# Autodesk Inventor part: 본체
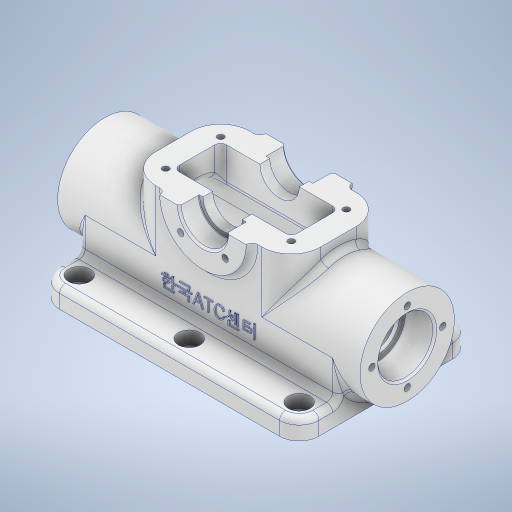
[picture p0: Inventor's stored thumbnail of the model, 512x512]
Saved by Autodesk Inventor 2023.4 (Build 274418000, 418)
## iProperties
Created: 2024-06
Part Number: 본체
Material: 알루미늄 6061
Document SubType Name: Modeling
Designer: user
Density: 2.7 g/cm^3
Appearance: 알루미늄 - 평지
Mass: 551.897 g
Surface Area: 613.714 cm^2
Volume: 204.406 cm^3
Author: user
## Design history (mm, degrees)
sketch "스케치1"
  geometry: L1 (66, 44)-(-66, 44); L2 (-66, 44)-(-66, -44); L3 (-66, -44)-(66, -44); L4 (66, -44)-(66, 44); L5 (66, 44)-(-66, -44); L6 (-66, 44)-(66, -44); 1 further point
  constraints: 12 end point, 2 midpoint, 2 parallel, 1 horizontal, 1 perpendicular
  dimensions: "d0" = 132 distance of L2.end L3.end; "d1" = 88 distance of L1.end L2.end
extrude "돌출1" new body sketch "스케치1" distance "d2" = 10; taper "d3" = 0 deg
sketch "스케치2"
  geometry: L1 (0, -44)-(0, 44) reference; C1 r 24 at (28, 0); 2 further points
  constraints: 1 centre point, 1 horizontal alignment, 1 midpoint
  dimensions: "d4" = 48 diameter of C1; "d5" = 28 distance from line of L1 C1.centre
extrude "돌출2" join sketch "스케치2" stored distance "d6" = 154; taper "d7" = 0 deg
sketch "스케치3"
  geometry: L1 (10, 44)-(10, 15.875) reference; L2 (28, -24)-(10, -24); L3 (10, -24)-(10, 24); L4 (10, 24)-(28, 24); L5 (28, 24)-(28, -24); A1 r 24 centre (28, 0) between (28, -24) and (10, 15.875) reference; A2 r 24 centre (28, 0) between (28, -24) and (10, 15.875) reference; 3 further points
  constraints: 8 end point, 2 parallel, 2 tangent, 1 horizontal, 1 perpendicular, 1 point on circle, 1 point on line
extrude "돌출3" join sketch "스케치3" stored distance "d8" = 132; taper "d9" = 0 deg
node "작업 평면1"
sketch "스케치4"
  geometry: L1 (108, 0)-(24, 0); L2 (24, 0)-(24, -48); L3 (24, -48)-(108, -48); L4 (108, -48)-(108, 0); L5 (132, -48)-(0, -48) reference; L6 (0, -48)-(-11, -48) reference; L7 (-11, -48)-(-11, 0) reference; L8 (-11, 0)-(0, 0) reference; L9 (0, 0)-(132, 0) reference; L10 (132, 0)-(143, 0) reference; L11 (143, 0)-(143, -48) reference; L12 (143, -48)-(132, -48) reference; 1 further point
  constraints: 8 end point, 2 parallel, 2 point on line, 1 horizontal, 1 perpendicular
  dimensions: "d10" = 84 distance between parallel lines of L2 L4; "d11" = 42 distance from line of point (66, -24) L2
extrude "돌출4" join sketch "스케치4" distance "d12" = 31; taper "d13" = 0 deg
sketch "스케치5"
  geometry: L1 (66, 0)-(-66, 0) reference; L2 (-66, 4)-(-77, 4) reference; L3 (-77, 4)-(-77, 52) reference; L4 (-77, 52)-(-42, 52) reference; L5 (-42, 52)-(-42, 59) reference; L6 (-42, 59)-(42, 59) reference; L7 (42, 59)-(42, 52) reference; L8 (42, 52)-(77, 52) reference; L9 (77, 52)-(77, 4) reference; L10 (77, 4)-(66, 4) reference; L11 (66, 4)-(66, 0) reference; L12 (66, 0)-(-66, 0) reference; L13 (-66, 0)-(-66, 4) reference; C1 r 22 at (0, 59); 4 further points
  constraints: 1 centre point, 1 midpoint, 1 vertical alignment
  dimensions: "d14" = 44 diameter of C1; "d15" = 59 distance from line of L1 C1.centre
extrude "돌출5" join sketch "스케치5" stored distance "d16" = 54; taper "d17" = 0 deg
sketch "스케치6"
  geometry: L1 (37, -27)-(59, -27) reference; L2 (47, -27)-(47, -17); L3 (47, -17)-(49, -17); L4 (49, -17)-(49, 17); L5 (49, 17)-(47, 17); L6 (47, 17)-(47, 27); L7 (59, 27)-(37, 27) reference; L8 (59, -27)-(59, 27); 1 further point
  constraints: 12 end point, 4 point on line, 3 perpendicular, 2 vertical
  dimensions: "d18" = 24 diameter of L2 L8; "d19" = 20 diameter of L4 L8; "d20" = 10 distance of L5.end L6.end; "d21" = 10 distance of L2.start L2.end
revolve "회전1" sketch "스케치6" stored, may be unused: angle "d22" = 90 deg
sketch "스케치7"
  geometry: L1 (36, -12)-(96, -12); L2 (96, -12)-(96, -36); L3 (96, -36)-(36, -36); L4 (36, -36)-(36, -12); L5 (36, -12)-(96, -36); L6 (96, -12)-(36, -36); 1 further point
  constraints: 12 end point, 2 midpoint, 2 parallel, 1 horizontal, 1 perpendicular
  dimensions: "d23" = 60 distance between parallel lines of L4 L2; "d24" = 24 distance of L3.end L1.start
extrude "돌출6" cut sketch "스케치7" extent not by distance; stored distance "d25" = 0; taper "d26" = 0 deg
sketch "스케치8"
  geometry: L1 (0, 44)-(0, -44) reference; L2 (28, -18)-(0, -18); L3 (28, 18)-(0, 18); A1 r 18 centre (28, 0) between (28, -18) and (28, 18); 2 further points
  constraints: 4 end point, 2 point on circle, 2 point on line, 2 tangent, 1 centre point, 1 horizontal, 1 horizontal alignment, 1 midpoint, 1 perpendicular
  dimensions: "d27" = 36 diameter of A1; "d28" = 28 distance from line of L1 A1.centre
extrude "돌출7" cut sketch "스케치8" stored distance "d29" = 120; taper "d30" = 0 deg
sketch "스케치9"
  geometry: L1 (-77, 52)-(-77, 4) reference; L2 (-77, 42)-(-62, 42); L3 (-62, 42)-(-62, 39); L4 (-62, 39)-(-60, 39); L5 (-60, 46)-(-60, 28) reference; L6 (77, 4)-(77, 52) reference; L7 (77, 42)-(62, 42); L8 (62, 42)-(62, 39); L9 (62, 39)-(60, 39); L10 (77, 4)-(66, 4) reference; L11 (66, 4)-(66, 0) reference; L12 (66, 0)-(60, 0) reference; L13 (60, 0)-(60, 46) reference; L14 (60, 46)-(30, 46) reference; L15 (30, 46)-(30, 59) reference; L16 (30, 59)-(42, 59) reference; L17 (42, 59)-(42, 52) reference; L18 (42, 52)-(77, 52) reference; L19 (77, 52)-(77, 4) reference; L20 (-66, 4)-(-77, 4) reference; L21 (-77, 4)-(-77, 52) reference; L22 (-77, 52)-(-42, 52) reference; L23 (-42, 52)-(-42, 59) reference; L24 (-42, 59)-(-30, 59) reference; L25 (-30, 59)-(-30, 46) reference; L26 (-30, 46)-(-60, 46) reference; L27 (-60, 46)-(-60, 0) reference; L28 (-60, 0)-(-66, 0) reference; L29 (-66, 0)-(-66, 4) reference; L30 (-77, 28)-(77, 28); 5 further points
  constraints: 14 end point, 6 point on line, 2 horizontal, 2 midpoint, 2 perpendicular, 1 vertical
  dimensions: "d31" = 28 diameter of L7 L30; "d32" = 22 diameter of L9 L30; "d33" = 28 diameter of L2 L30; "d34" = 15 distance of L2.start L2.end; "d35" = 15 distance of L7.start L7.end
revolve "회전2" sketch "스케치9" stored, may be unused: angle "d36" = 90 deg
fillet "모깎기1" dims "d37" = 0.3
fillet "모깎기2" dims "d38" = 15
fillet "모깎기3" dims "d39" = 3
sketch "스케치10"
  geometry: L1 (0, -10)-(132, -10) reference; L2 (41.419, 13.539)-(91.194, 13.539); L3 (91.194, 13.539)-(91.194, 6.334); L4 (91.194, 6.334)-(41.419, 6.334); L5 (41.419, 6.334)-(41.419, 13.539); 3 further points
  constraints: 1 midpoint, 1 vertical alignment, 2 other
  dimensions: "d40" = 20 distance from line of L1 point (66, 10)
feature "엠보싱1" sketch "스케치10" dims "d41" = 0.5, "d42" = 0
sketch "스케치11" dims "d10" = 84, "d11" = 42
  geometry: C1 r 14 at (0, 0) reference; A1 r 18 centre (0, 0) between (-12, 13.416) and (12, 13.416); A2 r 18 centre (0, 0) between (12, 13.416) and (-12, 13.416) reference; 2 further points
  constraints: 1 centre point, 1 coincident, 1 point on circle
  dimensions: "d43" = 36 diameter of A1
hole "구멍1" sketch "스케치11" at (0, 18) diameter "d44" = 3.242; stored, may be unused: countersink angle "d48" = 90 deg, drill point angle "d50" = 118 deg; dims "d45" = 8, "d46" = 4, "d47" = 2, "d49" = 10
fillet "모깎기4" dims "d54" = 10
fillet "모깎기5" dims "d55" = 3
fillet "모깎기6" dims "d56" = 3
fillet "모깎기7" dims "d57" = 3
fillet "모깎기8" dims "d58" = 3
fillet "모깎기9" dims "d59" = 3
sketch "스케치12"
  geometry: L1 (77.7, -41)-(76, -41) reference; L2 (76, -41)-(76, -36) reference; L3 (76, -36)-(93, -36) reference; L4 (96, -33)-(96, -15) reference; L5 (93, -12)-(76, -12) reference; L6 (76, -12)-(76, -7) reference; L7 (76, -7)-(77.7, -7) reference; L8 (78, -6.7)-(78, 3) reference; L9 (78, 3)-(88, 3) reference; L10 (88, 3)-(88, 0) reference; L11 (88, 0)-(93, 0) reference; L12 (108, -15)-(108, -33) reference; L13 (93, -48)-(88, -48) reference; L14 (88, -48)-(88, -51) reference; L15 (88, -51)-(78, -51) reference; L16 (78, -51)-(78, -41.3) reference; L17 (54, -41.3)-(54, -51) reference; L18 (54, -51)-(44, -51) reference; L19 (44, -51)-(44, -48) reference; L20 (44, -48)-(39, -48) reference; L21 (24, -33)-(24, -15) reference; L22 (39, 0)-(44, 0) reference; L23 (44, 0)-(44, 3) reference; L24 (44, 3)-(54, 3) reference; L25 (54, 3)-(54, -6.7) reference; L26 (54.3, -7)-(56, -7) reference; L27 (56, -7)-(56, -12) reference; L28 (56, -12)-(39, -12) reference; L29 (36, -15)-(36, -33) reference; L30 (39, -36)-(56, -36) reference; L31 (56, -36)-(56, -41) reference; L32 (56, -41)-(54.3, -41) reference; L33 (98, -38)-(34, -38); L34 (34, -38)-(34, -10); L35 (34, -10)-(98, -10); L36 (98, -10)-(98, -38); A1 r 0.3 centre (77.7, -41.3) between (78, -41.3) and (77.7, -41) reference; A2 r 3 centre (93, -33) between (93, -36) and (96, -33) reference; A3 r 3 centre (93, -15) between (96, -15) and (93, -12) reference; A4 r 0.3 centre (77.7, -6.7) between (77.7, -7) and (78, -6.7) reference; A5 r 15 centre (93, -15) between (108, -15) and (93, 0) reference; A6 r 15 centre (93, -33) between (93, -48) and (108, -33) reference; A7 r 0.3 centre (54.3, -41.3) between (54.3, -41) and (54, -41.3) reference; A8 r 15 centre (39, -33) between (24, -33) and (39, -48) reference; A9 r 15 centre (39, -15) between (39, 0) and (24, -15) reference; A10 r 0.3 centre (54.3, -6.7) between (54, -6.7) and (54.3, -7) reference; A11 r 3 centre (39, -15) between (39, -12) and (36, -15) reference; A12 r 3 centre (39, -33) between (36, -33) and (39, -36) reference; 1 further point
  constraints: 8 end point, 2 parallel, 1 horizontal, 1 perpendicular
  dimensions: "d60" = 64 distance of L33.start L33.end; "d61" = 28 distance of L33.end L34.end; "d62" = 32 distance from line of point (66, -24) L34; "d63" = 14 distance from line of L35 point (66, -24)
hole "구멍2" sketch "스케치12" at (98, -38), (34, -38), (34, -10), (98, -10) diameter "d64" = 3.242; stored, may be unused: countersink angle "d68" = 90 deg, drill point angle "d70" = 118 deg; dims "d65" = 8, "d66" = 4, "d67" = 2, "d69" = 10
sketch "스케치13" dims "d71" = 32
  geometry: L1 (0, 59)-(0, 37); L2 (0, 59)-(-11.314, 47.686); A1 r 10 centre (0, 59) between (-10, 59) and (10, 59) reference; A2 r 22 centre (0, 59) between (-22, 59) and (22, 59) reference; 2 further points
  constraints: 4 end point, 1 coincident, 1 point on circle, 1 vertical, 3 other
  dimensions: "d72" = 45 deg angle of L1 L2
hole "구멍3" sketch "스케치13" at (-11.314, 47.686) diameter "d73" = 3.242; stored, may be unused: countersink angle "d77" = 90 deg, drill point angle "d79" = 118 deg; dims "d74" = 8, "d75" = 4, "d76" = 2, "d78" = 10
fillet "모깎기10" dims "d83" = 3
fillet "모깎기11" dims "d84" = 3
sketch "스케치14"
  geometry: L1 (56, -34)-(-56, -34); L2 (-56, -34)-(-56, 34); L3 (-56, 34)-(56, 34); L4 (56, 34)-(56, -34); L5 (-60, 15)-(-60, -15) reference; L6 (-57, -18)-(57, -18) reference; L7 (60, -15)-(60, 15) reference; L8 (57, 18)-(-57, 18) reference; L9 (-66.026, 0)-(-67, 1.621) reference; L10 (-67, 1.621)-(-77, 1.621) reference; L11 (-77, 1.621)-(-77, 15.875) reference; L12 (-77, 15.875)-(-69, 15.875) reference; L13 (-66, 20.125)-(-66, 21.804) reference; L14 (-63, 34)-(-63, 27) reference; L15 (56, 41)-(-56, 41) reference; L16 (63, 27)-(63, 34) reference; L17 (66, 21.804)-(66, 20.125) reference; L18 (69, 15.875)-(77, 15.875) reference; L19 (77, 15.875)-(77, 1.621) reference; L20 (77, 1.621)-(67, 1.621) reference; L21 (67, 1.621)-(66.026, 0) reference; L22 (66.026, 0)-(67, -1.621) reference; L23 (67, -1.621)-(77, -1.621) reference; L24 (77, -1.621)-(77, -15.875) reference; L25 (77, -15.875)-(69, -15.875) reference; L26 (66, -20.125)-(66, -21.804) reference; L27 (63, -34)-(63, -27) reference; L28 (-56, -41)-(56, -41) reference; L29 (-63, -27)-(-63, -34) reference; L30 (-66, -21.804)-(-66, -20.125) reference; L31 (-69, -15.875)-(-77, -15.875) reference; L32 (-77, -15.875)-(-77, -1.621) reference; L33 (-77, -1.621)-(-67, -1.621) reference; L34 (-67, -1.621)-(-66.026, 0) reference; L35 (63, 27)-(-63, 27) reference; L36 (-63, -27)-(63, -27) reference; A1 r 7 centre (56, -34) between (56, -41) and (63, -34) reference; A2 r 7 centre (-56, 34) between (-56, 41) and (-63, 34) reference; A3 r 3 centre (-57, 15) between (-57, 18) and (-60, 15) reference; A4 r 3 centre (-57, -15) between (-60, -15) and (-57, -18) reference; A5 r 3 centre (57, -15) between (57, -18) and (60, -15) reference; A6 r 3 centre (57, 15) between (60, 15) and (57, 18) reference; A7 r 7 centre (-56, 34) between (-56, 41) and (-63, 34) reference; A8 r 7 centre (56, 34) between (63, 34) and (56, 41) reference; A9 r 7 centre (56, -34) between (56, -41) and (63, -34) reference; A10 r 7 centre (-56, -34) between (-63, -34) and (-56, -41) reference; 3 further points
  constraints: 8 end point, 2 midpoint, 2 parallel, 1 horizontal, 1 perpendicular, 8 other
hole "구멍4" sketch "스케치14" at (0, -34), (0, 34), (-56, 34), (-56, -34), (56, -34), (56, 34) diameter "d85" = 6.6; stored, may be unused: countersink angle "d89" = 90 deg, drill point angle "d91" = 118 deg; dims "d86" = 8, "d87" = 11, "d88" = 6.6, "d90" = 10
chamfer "모따기1" distance "d92" = 1; stored, may be unused: second distance "d93" = 2, angle "d94" = 45 deg
chamfer "모따기2" distance "d95" = 1; stored, may be unused: second distance "d96" = 2, angle "d97" = 45 deg
node "솔리드1"
pattern_circular "원형 패턴1" dims angle "d52" = 360 deg
mirror "미러1"
pattern_circular "원형 패턴2" dims angle "d81" = 360 deg
mirror "미러2"
node "절단 모서리 투영1"
node "절단 모서리 투영2"
node "절단 모서리 투영3"
node "절단 모서리 투영4"
node "절단 모서리 투영5"
feature "A9D066F2-1C7D-4E18-AEED-F7BC21143FA4" dims "d85" = 6.6, "d86" = 8, "d87" = 11, "d88" = 6.6, "d89" = 90 deg, "d90" = 10, "d91" = 118 deg
